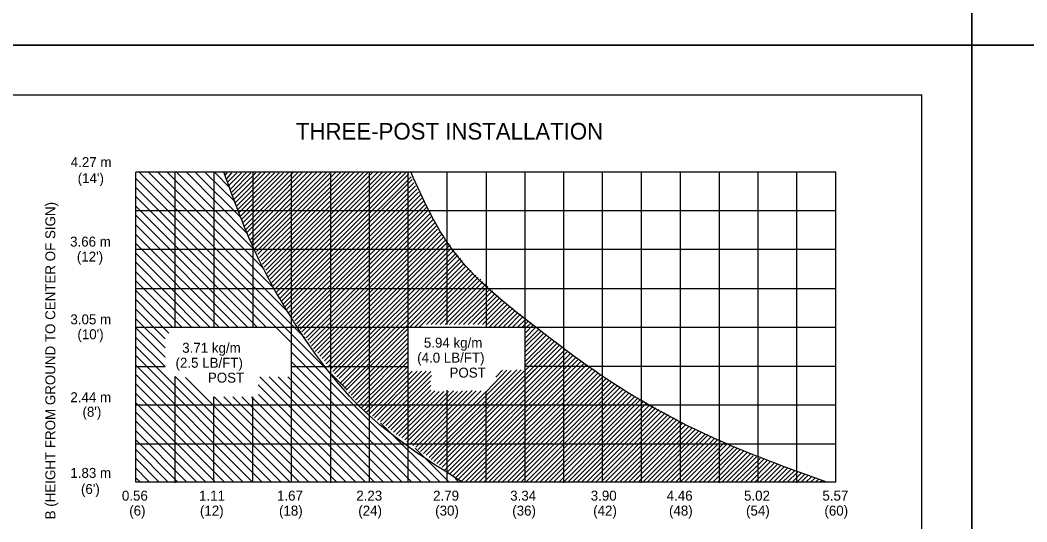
# Model space of a CAD drawing. Extents: x 644358 to 648627, y 294594 to 295782.
# Drawn here: x 645753.8 to 646056.9, y 295044.1 to 295195.1 of the extents above; entities that cross this region are included whole.
import ezdxf

# ---------------------------------------------------------------- set-up
doc = ezdxf.new("R2010")
doc.units = 0
for name, color, linetype in [('1', 7, 'Continuous'), ('10', 7, 'Continuous'), ('2', 7, 'Continuous'), ('4', 7, 'Continuous'), ('PLT-BNDY', 7, 'Continuous')]:
    doc.layers.add(name, color=color, linetype=linetype)

msp = doc.modelspace()

# ---------------------------------------------------------------- linework, layer by layer
at = {"layer": '1'}
for p, q in [((645239.31, 295172.63), (646025.31, 295172.63)), ((646025.31, 294608.63), (646025.31, 295172.63)), ((645845.96, 295090.75), (645845.96, 295090.75)), ((645859.21, 295079.5), (645859.21, 295079.5)), ((645872.21, 295067.63), (645872.21, 295067.63))]:
    msp.add_line(p, q, dxfattribs=at)
at = {"layer": '10'}
for p, q in [((645852.13, 295083.96), (645788.59, 295147.5)), ((645839.59, 295099.38), (645789.59, 295149.38)), ((645834.21, 295107.5), (645792.46, 295149.38)), ((645830.21, 295114.38), (645795.21, 295149.38)), ((645827.21, 295120.13), (645798.09, 295149.25)), ((645824.34, 295126), (645800.96, 295149.25)), ((645822.21, 295130.75), (645803.96, 295149.25)), ((645820.21, 295135.75), (645806.71, 295149.13)), ((645818.46, 295140.38), (645809.59, 295149.13)), ((645816.84, 295144.75), (645812.46, 295149.13)), ((645815.46, 295148.5), (645816.09, 295149.13)), ((645815.96, 295147.38), (645817.46, 295149.13)), ((645816.21, 295146.38), (645818.96, 295149.13)), ((645816.59, 295145.38), (645820.46, 295149.13)), ((645817.09, 295144.25), (645821.84, 295149.13)), ((645817.46, 295143.38), (645823.21, 295149.13)), ((645817.71, 295142.38), (645824.71, 295149.13)), ((645818.21, 295141.25), (645826.09, 295149.13)), ((645818.59, 295140.25), (645827.46, 295149.13)), ((645818.96, 295139.25), (645828.96, 295149.13)), ((645819.34, 295138.13), (645830.34, 295149.13)), ((645819.71, 295137.25), (645831.71, 295149.13)), ((645820.21, 295136.25), (645833.09, 295149.13)), ((645820.46, 295135.13), (645834.59, 295149.25)), ((645820.84, 295134.13), (645835.96, 295149.25)), ((645821.34, 295133.13), (645837.34, 295149.25)), ((645821.71, 295132.13), (645838.71, 295149.25)), ((645821.96, 295131.13), (645840.21, 295149.25)), ((645822.59, 295130.25), (645841.59, 295149.25)), ((645823.09, 295129.13), (645842.96, 295149.25)), ((645823.46, 295128.25), (645844.46, 295149.25)), ((645823.96, 295127.38), (645845.96, 295149.25)), ((645824.46, 295126.38), (645847.34, 295149.25)), ((645824.96, 295125.5), (645848.71, 295149.25)), ((645825.34, 295124.63), (645850.21, 295149.25)), ((645825.84, 295123.63), (645851.59, 295149.25)), ((645826.34, 295122.63), (645852.96, 295149.38)), ((645826.71, 295121.63), (645854.34, 295149.38)), ((645827.21, 295120.75), (645855.84, 295149.38)), ((645827.71, 295119.88), (645857.21, 295149.38)), ((645828.09, 295118.88), (645858.59, 295149.38)), ((645828.59, 295118), (645859.96, 295149.38)), ((645829.09, 295117.13), (645861.46, 295149.38)), ((645829.46, 295116), (645862.84, 295149.38)), ((645829.96, 295115.13), (645864.21, 295149.38)), ((645830.46, 295114.13), (645865.59, 295149.38)), ((645830.96, 295113.25), (645867.09, 295149.38)), ((645831.46, 295112.38), (645868.59, 295149.38)), ((645831.96, 295111.38), (645869.96, 295149.38)), ((645832.46, 295110.5), (645870.84, 295148.88)), ((645832.96, 295109.63), (645871.46, 295148)), ((645830.82, 295102.63), (645788.59, 295144.75)), ((645833.59, 295108.88), (645871.84, 295147.13)), ((645834.09, 295108.13), (645872.34, 295146.13)), ((645834.71, 295107.13), (645872.84, 295145.25)), ((645827.96, 295102.63), (645788.59, 295142)), ((645835.34, 295106.38), (645873.21, 295144.25)), ((645835.84, 295105.5), (645873.71, 295143.38)), ((645836.46, 295104.63), (645874.34, 295142.5)), ((645836.96, 295103.75), (645874.71, 295141.5)), ((645825.2, 295102.63), (645788.59, 295139.13)), ((645837.46, 295103), (645875.21, 295140.63)), ((645838.09, 295102.13), (645875.71, 295139.63)), ((645838.59, 295101.25), (645876.09, 295138.75)), ((645822.34, 295102.63), (645788.59, 295136.38)), ((645839.21, 295100.5), (645876.59, 295137.88)), ((645839.84, 295099.5), (645877.21, 295136.88)), ((645840.34, 295098.75), (645877.59, 295136)), ((645819.46, 295102.63), (645788.59, 295133.5)), ((645840.96, 295097.88), (645878.09, 295135.13)), ((645841.46, 295097.13), (645878.59, 295134.13)), ((645842.09, 295096.13), (645879.09, 295133.25)), ((645842.59, 295095.38), (645879.46, 295132.25)), ((645816.7, 295102.63), (645788.59, 295130.63)), ((645843.38, 295094.92), (645880.09, 295131.38)), ((645844.05, 295093.97), (645880.59, 295130.63)), ((645844.74, 295093.28), (645881.21, 295129.75)), ((645813.84, 295102.63), (645788.59, 295127.88)), ((645845.4, 295092.57), (645881.96, 295129)), ((645845.92, 295091.71), (645882.46, 295128.25)), ((645846.73, 295091.02), (645883.21, 295127.5)), ((645847.28, 295090.19), (645883.71, 295126.63)), ((645810.96, 295102.63), (645788.59, 295125)), ((645847.91, 295089.33), (645884.34, 295125.88)), ((645848.46, 295088.62), (645885.09, 295125)), ((645849.16, 295087.7), (645885.59, 295124.38)), ((645849.86, 295087.27), (645886.34, 295123.5)), ((645808.11, 295102.63), (645788.59, 295122.25)), ((645850.09, 295085.88), (645886.84, 295122.75)), ((645850.71, 295085.25), (645887.46, 295121.88)), ((645869.65, 295102.63), (645888.09, 295121.13)), ((645870.97, 295102.63), (645888.84, 295120.38)), ((645805.44, 295102.63), (645788.59, 295119.38)), ((645872.46, 295102.63), (645889.59, 295119.75)), ((645873.84, 295102.63), (645890.21, 295119)), ((645876.07, 295103.48), (645890.96, 295118.38)), ((645877.48, 295103.48), (645891.71, 295117.63)), ((645878.82, 295103.48), (645892.46, 295117.13)), ((645802.59, 295102.63), (645788.59, 295116.63)), ((645880.19, 295103.48), (645893.09, 295116.38)), ((645881.73, 295103.48), (645893.96, 295115.63)), ((645883.07, 295103.48), (645894.59, 295115)), ((645884.48, 295103.48), (645895.34, 295114.25)), ((645799.71, 295102.63), (645788.59, 295113.75)), ((645798.56, 295100.94), (645788.59, 295111)), ((645885.82, 295103.48), (645895.96, 295113.63)), ((645887.28, 295103.48), (645896.84, 295112.88)), ((645888.69, 295103.48), (645897.46, 295112.25)), ((645890.19, 295103.48), (645898.21, 295111.5)), ((645797.39, 295099.22), (645788.59, 295108.13)), ((645891.57, 295103.48), (645898.96, 295110.88)), ((645892.94, 295103.48), (645899.71, 295110.25)), ((645894.39, 295103.48), (645900.46, 295109.63)), ((645894.89, 295102.63), (645901.34, 295109)), ((645896.34, 295102.63), (645902.09, 295108.38)), ((645797.39, 295096.45), (645788.59, 295105.25)), ((645897.71, 295102.63), (645902.84, 295107.75)), ((645899.15, 295102.63), (645903.59, 295107.13)), ((645900.46, 295102.63), (645904.46, 295106.63)), ((645901.96, 295102.63), (645905.21, 295105.88)), ((645903.41, 295102.63), (645906.09, 295105.25)), ((645797.39, 295093.7), (645788.59, 295102.5)), ((645877.46, 295056), (645830.84, 295102.63)), ((645851.46, 295084.38), (645869.65, 295102.63)), ((645851.96, 295083.75), (645870.59, 295102.25)), ((645904.8, 295102.63), (645906.84, 295104.63)), ((645905.84, 295102.29), (645907.59, 295104)), ((645905.84, 295100.94), (645908.34, 295103.5)), ((645905.84, 295099.35), (645909.02, 295102.74)), ((645905.84, 295098), (645909.96, 295102.13)), ((645908.97, 295102.63), (645909.09, 295102.75)), ((645797.39, 295090.85), (645788.59, 295099.63)), ((645852.71, 295082.88), (645870.59, 295100.75)), ((645853.46, 295082.25), (645870.59, 295099.38)), ((645905.84, 295096.75), (645910.71, 295101.63)), ((645905.84, 295095.25), (645911.46, 295100.88)), ((645905.84, 295094), (645912.21, 295100.38)), ((645905.84, 295092.38), (645913.09, 295099.63)), ((645905.84, 295091.13), (645913.84, 295099.13)), ((645797.39, 295088.08), (645788.59, 295096.88)), ((645853.96, 295081.38), (645870.59, 295098)), ((645854.71, 295080.75), (645870.59, 295096.63)), ((645880.85, 295060.51), (645916.9, 295096.56)), ((645881.6, 295059.76), (645917.84, 295096)), ((645905.84, 295089.63), (645914.71, 295098.5)), ((645905.84, 295088.25), (645915.33, 295097.75)), ((645905.84, 295086.98), (645916.03, 295097.22)), ((645826.59, 295056), (645788.59, 295094.13)), ((645874.59, 295056), (645835.46, 295095.13)), ((645855.34, 295079.88), (645870.59, 295095.27)), ((645856.09, 295079.25), (645870.59, 295093.61)), ((645882.57, 295059.24), (645918.59, 295095.38)), ((645883.28, 295058.69), (645919.46, 295094.75)), ((645884.11, 295058.03), (645920.21, 295094.13)), ((645884.71, 295057.25), (645920.96, 295093.5)), ((645885.59, 295056.75), (645921.71, 295092.88)), ((645823.71, 295056), (645788.59, 295091.25)), ((645871.71, 295056), (645835.46, 295092.25)), ((645856.59, 295078.38), (645870.59, 295092.51)), ((645857.34, 295077.75), (645870.59, 295091)), ((645876.91, 295063.45), (645903.29, 295089.83)), ((645877.57, 295062.85), (645904.66, 295089.83)), ((645878.34, 295062.25), (645905.92, 295089.83)), ((645879.22, 295061.64), (645907.42, 295089.83)), ((645880.08, 295061.12), (645908.67, 295089.83)), ((645886.59, 295056.25), (645922.59, 295092.38)), ((645887.84, 295056.13), (645923.46, 295091.75)), ((645889.21, 295056.13), (645924.21, 295091.25)), ((645890.59, 295056.13), (645925.21, 295090.63)), ((645891.96, 295056.13), (645925.96, 295090.13)), ((645820.96, 295056), (645788.59, 295088.5)), ((645829.46, 295056), (645797.2, 295088.26)), ((645832.34, 295056), (645800.41, 295087.83)), ((645835.09, 295056), (645803.58, 295087.51)), ((645857.71, 295056), (645825.96, 295087.75)), ((645860.46, 295056), (645828.73, 295087.74)), ((645863.21, 295056), (645831.48, 295087.74)), ((645866.09, 295056), (645834.35, 295087.74)), ((645868.84, 295056), (645835.46, 295089.38)), ((645857.96, 295077), (645870.59, 295089.63)), ((645858.59, 295076.25), (645871.79, 295089.45)), ((645859.82, 295075.87), (645873.29, 295089.45)), ((645860.5, 295075.41), (645874.65, 295089.45)), ((645861.38, 295074.67), (645876.04, 295089.45)), ((645862.26, 295074.29), (645877.46, 295089.38)), ((645863.03, 295073.57), (645877.59, 295088.13)), ((645876.05, 295064.21), (645901.64, 295089.65)), ((645893.46, 295056.13), (645926.84, 295089.5)), ((645894.14, 295083.33), (645900.34, 295089.75)), ((645894.84, 295056.13), (645927.71, 295088.88)), ((645896.21, 295056.13), (645928.59, 295088.5)), ((645896.96, 295087.63), (645898.96, 295089.75)), ((645897.59, 295056.13), (645929.34, 295087.88)), ((645898.96, 295056.13), (645930.21, 295087.25)), ((645900.46, 295056.13), (645931.09, 295086.75)), ((645818.09, 295056), (645788.59, 295085.63)), ((645854.84, 295056), (645825.48, 295085.36)), ((645863.89, 295073.05), (645877.34, 295086.5)), ((645864.58, 295072.25), (645877.46, 295085.13)), ((645865.38, 295071.78), (645877.46, 295083.75)), ((645901.84, 295056.13), (645931.84, 295086.13)), ((645903.21, 295056.13), (645932.84, 295085.63)), ((645904.59, 295056.13), (645933.59, 295085.13)), ((645906.09, 295056.13), (645934.46, 295084.5)), ((645907.46, 295056.13), (645935.34, 295084)), ((645815.34, 295056), (645788.59, 295082.75)), ((645837.84, 295056), (645812.21, 295081.75)), ((645840.71, 295056), (645815.08, 295081.75)), ((645843.46, 295056), (645817.83, 295081.75)), ((645846.34, 295056), (645820.48, 295081.75)), ((645849.09, 295056), (645823.46, 295081.75)), ((645851.96, 295056), (645825.49, 295082.47)), ((645866.15, 295071.06), (645878.59, 295083.5)), ((645866.95, 295070.37), (645879.96, 295083.38)), ((645867.83, 295069.99), (645881.34, 295083.38)), ((645868.72, 295069.38), (645882.71, 295083.38)), ((645869.57, 295068.75), (645884.21, 295083.5)), ((645870.23, 295068.15), (645885.46, 295083.38)), ((645871.17, 295067.59), (645886.96, 295083.5)), ((645872.05, 295067.1), (645888.34, 295083.5)), ((645872.88, 295066.55), (645889.84, 295083.63)), ((645873.59, 295065.89), (645891.09, 295083.5)), ((645874.34, 295065.25), (645892.59, 295083.5)), ((645875.23, 295064.64), (645894.09, 295083.38)), ((645908.96, 295056.13), (645936.09, 295083.38)), ((645910.34, 295056.13), (645937.09, 295082.88)), ((645911.71, 295056.13), (645937.96, 295082.38)), ((645913.09, 295056.13), (645938.96, 295081.88)), ((645914.46, 295056.13), (645939.84, 295081.38)), ((645915.96, 295056), (645940.59, 295080.88)), ((645812.59, 295056), (645788.59, 295079.88)), ((645917.34, 295056), (645941.59, 295080.38)), ((645918.71, 295056), (645942.46, 295079.88)), ((645920.09, 295056), (645943.46, 295079.38)), ((645921.46, 295056), (645944.34, 295078.88)), ((645922.84, 295056), (645945.21, 295078.38)), ((645924.34, 295056), (645946.09, 295077.88)), ((645809.71, 295056), (645788.59, 295077.13)), ((645925.71, 295056), (645946.96, 295077.38)), ((645927.09, 295056), (645947.96, 295076.88)), ((645928.59, 295056), (645948.84, 295076.38)), ((645929.96, 295056), (645949.71, 295075.88)), ((645931.46, 295056), (645950.71, 295075.38)), ((645932.84, 295056), (645951.59, 295074.88)), ((645806.96, 295056), (645788.59, 295074.38)), ((645880.21, 295056), (645862.3, 295073.91)), ((645934.21, 295056), (645952.46, 295074.38)), ((645935.59, 295056), (645953.34, 295073.88)), ((645936.96, 295056), (645954.21, 295073.38)), ((645938.34, 295056), (645955.21, 295072.88)), ((645939.84, 295056), (645956.09, 295072.38)), ((645941.21, 295056), (645957.09, 295072)), ((645803.96, 295056), (645788.59, 295071.5)), ((645801.21, 295056), (645788.59, 295068.75)), ((645942.59, 295056), (645958.09, 295071.5)), ((645943.96, 295056), (645958.96, 295071.13)), ((645945.34, 295056), (645960.09, 295070.63)), ((645946.84, 295056), (645960.96, 295070.25)), ((645948.21, 295056), (645961.96, 295069.75)), ((645949.59, 295056), (645962.96, 295069.25)), ((645951.09, 295056), (645963.84, 295068.88)), ((645798.34, 295056), (645788.59, 295065.88)), ((645882.96, 295056), (645872.71, 295066.26)), ((645952.46, 295056), (645964.84, 295068.5)), ((645953.84, 295056), (645965.84, 295068)), ((645955.34, 295056), (645966.71, 295067.63)), ((645956.71, 295056), (645967.71, 295067.13)), ((645958.09, 295056), (645968.71, 295066.63)), ((645959.46, 295056), (645969.71, 295066.25)), ((645960.84, 295056), (645970.59, 295065.88)), ((645795.59, 295056), (645788.59, 295063.13)), ((645962.34, 295056), (645971.59, 295065.38)), ((645963.71, 295056), (645972.59, 295064.88)), ((645965.09, 295056), (645973.59, 295064.5)), ((645966.46, 295056), (645974.46, 295064)), ((645967.84, 295056), (645975.46, 295063.63)), ((645969.21, 295056), (645976.59, 295063.13)), ((645970.71, 295056), (645977.59, 295062.88)), ((645972.09, 295056), (645978.59, 295062.5)), ((645792.71, 295056), (645788.59, 295060.25)), ((645973.59, 295056), (645979.59, 295062.13)), ((645974.96, 295056), (645980.71, 295061.63)), ((645976.34, 295056), (645981.71, 295061.38)), ((645977.84, 295056), (645982.71, 295061)), ((645979.21, 295056), (645983.84, 295060.63)), ((645980.59, 295056), (645984.84, 295060.25)), ((645981.96, 295056), (645985.84, 295059.88)), ((645983.34, 295056), (645986.96, 295059.5)), ((645789.96, 295056), (645788.59, 295057.38)), ((645885.84, 295056), (645884.71, 295057.13)), ((645984.71, 295056), (645987.96, 295059.13)), ((645986.21, 295056), (645988.96, 295058.75)), ((645987.59, 295056), (645990.09, 295058.5)), ((645988.96, 295056), (645991.09, 295058.13)), ((645990.34, 295056), (645992.09, 295057.63)), ((645991.71, 295056), (645993.09, 295057.25)), ((645993.21, 295056), (645994.21, 295057)), ((645994.59, 295056), (645995.21, 295056.63)), ((645996.09, 295056), (645996.21, 295056.25))]:
    msp.add_line(p, q, dxfattribs=at)
at = {"layer": '2'}
for p, q in [((645999.34, 295149.38), (645788.59, 295149.38)), ((645788.59, 295056), (645788.59, 295149.38)), ((645800.46, 295102.63), (645800.46, 295149.38)), ((645812.09, 295149.38), (645812.09, 295102.63)), ((645823.84, 295149.38), (645823.84, 295102.63)), ((645835.46, 295090.88), (645835.46, 295149.38)), ((645847.34, 295055.88), (645847.34, 295149.38)), ((645858.96, 295056), (645858.96, 295149.38)), ((645870.59, 295090.88), (645870.59, 295149.38)), ((645882.34, 295103.48), (645882.34, 295149.38)), ((645894.09, 295149.38), (645894.09, 295102.63)), ((645905.84, 295102.63), (645905.84, 295149.38)), ((645917.46, 295055.88), (645917.46, 295149.38)), ((645929.09, 295056), (645929.09, 295149.38)), ((645940.84, 295055.88), (645940.84, 295149.38)), ((645952.59, 295056), (645952.59, 295149.38)), ((645964.34, 295055.88), (645964.34, 295149.38)), ((645975.96, 295056), (645975.96, 295149.38)), ((645987.59, 295055.88), (645987.59, 295149.38)), ((645999.34, 295056), (645999.34, 295149.38)), ((645999.34, 295137.75), (645788.84, 295137.75)), ((645999.34, 295126.13), (645788.84, 295126.13)), ((645999.34, 295114.25), (645788.84, 295114.25)), ((645894.09, 295102.63), (645788.84, 295102.63)), ((645999.34, 295102.63), (645894.09, 295102.63)), ((645905.84, 295056), (645905.84, 295102.63)), ((645788.84, 295090.88), (645797.39, 295090.88)), ((645835.46, 295056), (645835.46, 295090.88)), ((645835.46, 295090.88), (645870.59, 295090.88)), ((645870.59, 295056), (645870.59, 295090.88)), ((645999.34, 295090.88), (645905.84, 295090.88)), ((645800.46, 295055.88), (645800.46, 295087.83)), ((645882.34, 295056), (645882.34, 295083.75)), ((645812.09, 295056), (645812.09, 295081.75)), ((645823.84, 295056), (645823.84, 295081.75)), ((645894.09, 295056), (645894.09, 295083.38)), ((645999.34, 295079.25), (645788.59, 295079.25)), ((645999.34, 295067.5), (645788.84, 295067.5)), ((645999.34, 295056), (645788.59, 295056))]:
    msp.add_line(p, q, dxfattribs=at)
at = {"layer": '4'}
msp.add_line((645996.71, 295056), (645996.71, 295056), dxfattribs=at)
for points in [[(645886.71, 295056.13), (645857.21, 295077.63), (645837.09, 295102.88), (645824.34, 295125.88), (645815.21, 295149.13)], [(645996.71, 295056), (645961.34, 295069.88), (645928.46, 295088.38), (645908.59, 295103), (645883.84, 295126.13), (645871.46, 295149.25)]]:
    msp.add_spline(points, degree=3, dxfattribs=at)
at = {"layer": 'PLT-BNDY'}
for points in [[(645199.31, 295781.63), (646040.31, 295781.63), (646040.31, 295187.63), (645199.31, 295187.63)], [(646040.31, 295781.63), (646881.31, 295781.63), (646881.31, 295187.63), (646040.31, 295187.63)], [(645199.31, 295187.63), (646040.31, 295187.63), (646040.31, 294593.63), (645199.31, 294593.63)], [(646040.31, 295187.63), (646881.31, 295187.63), (646881.31, 294593.63), (646040.31, 294593.63)]]:
    msp.add_lwpolyline(points, close=True, dxfattribs=at)

# ---------------------------------------------------------------- texts
at = {"layer": '2'}
msp.add_text('THREE-POST INSTALLATION', height=5, dxfattribs=at).set_placement((645836.81, 295159.18))
at = {"layer": '4'}
for s, p in [('4.27 m', (645769, 295150.89)), ("(14')", (645771.09, 295146.05)), ('3.66 m', (645768.81, 295126.96)), ("(12')", (645770.84, 295122.45)), ('3.05 m', (645768.9, 295103.55)), ("(10')", (645771.01, 295099.07)), ('5.94 kg/m', (645875.33, 295096.52)), ('3.71 kg/m', (645802.57, 295094.99)), ('(2.5 LB/FT)', (645800.55, 295090.49)), ('(4.0 LB/FT)', (645873.31, 295092.02)), ('POST', (645883.05, 295087.52)), ('POST', (645810.3, 295085.99)), ('2.44 m', (645768.89, 295080.11)), ("(8')", (645772.54, 295075.73)), ('1.83 m', (645768.88, 295057.33)), ("(6')", (645772.08, 295052.48)), ('0.56', (645784.41, 295050.48)), ('1.11', (645807.63, 295050.48)), ('1.67', (645831.1, 295050.48)), ('2.23', (645854.97, 295050.48)), ('2.79', (645878.11, 295050.48)), ('3.34', (645901.33, 295050.48)), ('3.90', (645925.57, 295050.48)), ('4.46', (645948.44, 295050.48)), ('5.02', (645971.73, 295050.48)), ('5.57', (645995.33, 295050.48)), ('(6)', (645786.61, 295045.98)), ('(12)', (645807.9, 295045.98)), ('(18)', (645831.71, 295045.98)), ('(24)', (645855.58, 295045.98)), ('(30)', (645878.73, 295045.98)), ('(36)', (645901.94, 295045.98)), ('(42)', (645926.31, 295045.98)), ('(48)', (645949.14, 295045.98)), ('(54)', (645972.34, 295045.98)), ('(60)', (645995.94, 295045.98))]:
    msp.add_text(s, height=3, dxfattribs=at).set_placement(p)
msp.add_text(' B (HEIGHT FROM GROUND TO CENTER OF SIGN)', height=3.005, rotation=90, dxfattribs=at).set_placement((645764.35, 295043.73))

doc.saveas('drawing.dxf')
